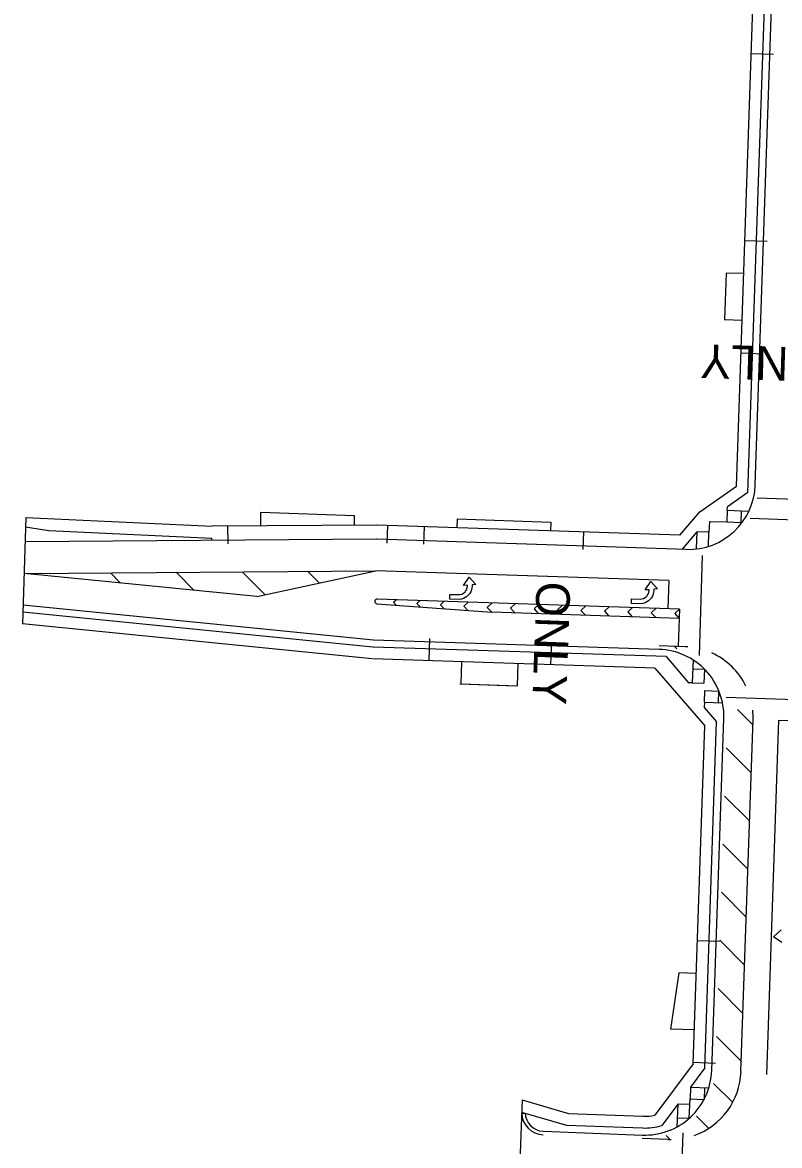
# Model space of a CAD drawing. Extents: x 979036 to 996074, y 1836928 to 1845163.
# Drawn here: x 992166.6 to 992489.6, y 1843156.7 to 1843635.7 of the extents above; entities that cross this region are included whole.
import ezdxf

# ---------------------------------------------------------------- set-up
doc = ezdxf.new("R2010")
doc.units = 0
for name, color, linetype in [('R_Proposed Road', 7, 'Continuous'), ('R_Striping', 7, 'Continuous'), ('STRIPE_White Crosswalk', 7, 'Continuous'), ('STRIPE_White Stopbar', 7, 'Continuous'), ('STRIPE_White Turn Arrow', 7, 'Continuous'), ('STRIPE_White_6in', 7, 'Continuous'), ('STRIPE_White_ONLY', 7, 'Continuous'), ('STRIPE_Yellow Dbl 6in', 7, 'Continuous'), ('STRIPE_Yellow_45_Diag_8in', 7, 'Continuous')]:
    doc.layers.add(name, color=color, linetype=linetype)

msp = doc.modelspace()

# ---------------------------------------------------------------- linework, layer by layer
at = {"layer": 'R_Proposed Road'}
for p, q in [((992471.17, 1843437.97), (992479.58, 1843683.42)), ((992476.08, 1843435.17), (992484.58, 1843683.25)), ((992479.19, 1843438.47), (992487.58, 1843683.15)), ((992477.5, 1843622.5), (992486.99, 1843622.17)), ((992484.25, 1843542.22), (992474.75, 1843542.55)), ((992466.78, 1843528.81), (992466.09, 1843508.82)), ((992474.27, 1843528.56), (992466.78, 1843528.81)), ((992473.59, 1843508.57), (992466.09, 1843508.82)), ((992482.6, 1843494.25), (992473.11, 1843494.58)), ((992455.58, 1843427.05), (992471.17, 1843437.97)), ((992476.08, 1843435.17), (992467.29, 1843429.15)), ((992268.3, 1843420.94), (992268.26, 1843426.82)), ((992268.26, 1843426.82), (992308.27, 1843425.46)), ((992447.07, 1843417.05), (992455.58, 1843427.05)), ((992467.24, 1843427.65), (992467.07, 1843422.65)), ((992467.24, 1843427.65), (992467.29, 1843429.15)), ((992467.24, 1843427.65), (992473.24, 1843427.44)), ((992473.24, 1843427.44), (992473.07, 1843422.45)), ((992473.24, 1843427.44), (992476.5, 1843427.33)), ((992168.12, 1843424.51), (992166.64, 1843379.22)), ((992168.12, 1843424.51), (992247.51, 1843420.8)), ((992308.3, 1843421.23), (992308.27, 1843425.46)), ((992352.07, 1843423.97), (992351.94, 1843420.18)), ((992352.07, 1843423.97), (992392.05, 1843422.64)), ((992392.05, 1843422.64), (992391.92, 1843418.87)), ((992459.61, 1843422.91), (992459.45, 1843418.25)), ((992459.61, 1843422.91), (992467.07, 1843422.65)), ((992467.07, 1843422.65), (992473.07, 1843422.45)), ((992473.07, 1843422.45), (992473.57, 1843422.43)), ((992167.99, 1843420.52), (992177.95, 1843419.05)), ((992177.95, 1843419.05), (992247.41, 1843415.79)), ((992317.81, 1843421.3), (992247.51, 1843420.8)), ((992254.36, 1843413.34), (992254.3, 1843420.84)), ((992447.07, 1843417.05), (992317.96, 1843421.29)), ((992322.3, 1843421.15), (992322.06, 1843413.66)), ((992337.95, 1843420.64), (992337.71, 1843413.14)), ((992405.92, 1843418.41), (992405.67, 1843410.91)), ((992448.21, 1843411.01), (992454.45, 1843418.42)), ((992454.2, 1843411.16), (992454.45, 1843418.42)), ((992459.45, 1843418.25), (992454.45, 1843418.42)), ((992459.24, 1843412.26), (992459.45, 1843418.25)), ((992317.71, 1843415.3), (992167.78, 1843414.22)), ((992247.41, 1843414.79), (992247.41, 1843415.79)), ((992449.77, 1843410.96), (992317.77, 1843415.3)), ((992454.2, 1843411.16), (992454.34, 1843415.16)), ((992316.11, 1843369.33), (992166.8, 1843384.22)), ((992316.31, 1843372.32), (992166.9, 1843387.23)), ((992315.78, 1843364.33), (992166.64, 1843379.22)), ((992441.16, 1843365.22), (992316.26, 1843369.32)), ((992438.22, 1843368.32), (992316.36, 1843372.32)), ((992340.08, 1843363.54), (992340.39, 1843373.03)), ((992392.05, 1843361.83), (992392.36, 1843371.33)), ((992436.43, 1843360.37), (992316.09, 1843364.32)), ((992441.16, 1843365.22), (992450.7, 1843354.12)), ((992353.76, 1843353.58), (992354.07, 1843363.08)), ((992377.75, 1843352.76), (992378.06, 1843362.29)), ((992436.43, 1843360.37), (992457.65, 1843335.68)), ((992452.65, 1843363.84), (992452.33, 1843354.07)), ((992452.53, 1843360.06), (992457.52, 1843359.9)), ((992457.52, 1843359.9), (992457.33, 1843353.9)), ((992353.16, 1843353.6), (992377.14, 1843352.78)), ((992353.76, 1843353.58), (992377.75, 1843352.76)), ((992452.33, 1843354.07), (992450.7, 1843354.12)), ((992452.33, 1843354.07), (992457.33, 1843353.9)), ((992457.53, 1843345.76), (992457.7, 1843350.76)), ((992457.7, 1843350.76), (992463.69, 1843350.55)), ((992463.52, 1843345.55), (992463.69, 1843350.55)), ((992457.53, 1843345.76), (992457.45, 1843343.59)), ((992457.53, 1843345.76), (992465.22, 1843345.5)), ((992457.45, 1843343.59), (992462.72, 1843337.46)), ((992452.71, 1843191.6), (992457.65, 1843335.68)), ((992457.66, 1843189.87), (992462.72, 1843337.46)), ((992460.62, 1843188.73), (992465.77, 1843338.86)), ((992464.01, 1843243.74), (992454.51, 1843244.07)), ((992446.54, 1843230.33), (992443.05, 1843206.44)), ((992454.03, 1843230.07), (992446.54, 1843230.33)), ((992453.21, 1843206.09), (992443.05, 1843206.44)), ((992462.23, 1843191.77), (992452.73, 1843192.1)), ((992452.71, 1843191.6), (992436.39, 1843169.66)), ((992457.64, 1843189.84), (992451.53, 1843181.63)), ((992451.53, 1843181.63), (992451.36, 1843176.63)), ((992451.53, 1843181.63), (992459.39, 1843181.36)), ((992457.52, 1843181.43), (992457.35, 1843176.43)), ((992379.76, 1843176.2), (992377.63, 1843121.23)), ((992379.76, 1843176.2), (992399.55, 1843170.46)), ((992446.27, 1843174.57), (992439.34, 1843165.25)), ((992445.89, 1843164.75), (992446.27, 1843174.57)), ((992446.27, 1843174.57), (992451.27, 1843174.37)), ((992451.04, 1843168.38), (992451.36, 1843176.63)), ((992451.36, 1843176.63), (992457.35, 1843176.43)), ((992379.56, 1843171.05), (992398.74, 1843165.48)), ((992379.56, 1843170.57), (992381.06, 1843170.61)), ((992399.55, 1843170.46), (992431.35, 1843169.23)), ((992446.04, 1843168.57), (992451.04, 1843168.38)), ((992398.74, 1843165.48), (992431.15, 1843164.23)), ((992388.75, 1843162.87), (992431.04, 1843161.23))]:
    msp.add_line(p, q, dxfattribs=at)
for centre, radius, start, end in [((992450.71, 1843439.45), 28.5, 268.1194, 358.0361), ((992437.29, 1843339.83), 28.5, 358.0361, 88.1194), ((992432.14, 1843189.71), 28.5, 267.7861, 358.0361), ((992389.06, 1843170.86), 9.5, 181.7845, 267.7861), ((992389.06, 1843170.86), 8, 181.7845, 267.7861), ((992432.14, 1843189.71), 20.5, 267.7861, 281.9633), ((992432.14, 1843189.71), 25.5, 267.7861, 286.4071)]:
    msp.add_arc(centre, radius, start, end, dxfattribs=at)
at = {"layer": 'R_Striping'}
for p, q in [((992167.34, 1843400.73), (992317.32, 1843401.8)), ((992266.65, 1843390.82), (992167.34, 1843400.73)), ((992266.65, 1843390.82), (992317.32, 1843401.8))]:
    msp.add_line(p, q, dxfattribs=at)
at = {"layer": 'STRIPE_White Crosswalk'}
for p, q in [((992477.09, 1843424.27), (992524.25, 1843422.65)), ((992456.61, 1843408.38), (992455.21, 1843365.68)), ((992466.81, 1843347.94), (992516.55, 1843346.31)), ((992448.3, 1843162.21), (992447.25, 1843135.19))]:
    msp.add_line(p, q, dxfattribs=at)
at = {"layer": 'STRIPE_White Stopbar'}
for p, q in [((992480.01, 1843433.01), (992496.49, 1843432.45)), ((992442.26, 1843397.7), (992441.86, 1843385.71)), ((992446.86, 1843385.54), (992446.34, 1843369.55)), ((992489.26, 1843338.17), (992516.24, 1843337.24))]:
    msp.add_line(p, q, dxfattribs=at)
at = {"layer": 'STRIPE_White Turn Arrow'}
for points in [[(992354.77, 1843395.51), (992357.12, 1843399.18), (992360.08, 1843395.97), (992358.42, 1843395.83), (992358.41, 1843395.16), (992358.37, 1843394.58), (992358.2, 1843393.78), (992357.82, 1843392.85), (992357.4, 1843392.12), (992356.85, 1843391.53), (992356.21, 1843390.84), (992355.52, 1843390.45), (992354.77, 1843390.03), (992353.83, 1843389.77), (992352.84, 1843389.62), (992348.94, 1843389.73), (992348.99, 1843391.73), (992352.58, 1843391.67), (992353.27, 1843391.71), (992354.01, 1843391.92), (992354.79, 1843392.29), (992355.44, 1843392.86), (992355.66, 1843393.16), (992356.04, 1843393.77), (992356.29, 1843394.53), (992356.41, 1843395.26), (992356.43, 1843395.65)], [(992432.25, 1843393.65), (992434.61, 1843397.32), (992437.56, 1843394.11), (992435.9, 1843393.96), (992435.9, 1843393.3), (992435.85, 1843392.72), (992435.68, 1843391.92), (992435.3, 1843390.98), (992434.88, 1843390.25), (992434.33, 1843389.67), (992433.69, 1843388.98), (992433, 1843388.59), (992432.25, 1843388.16), (992431.31, 1843387.9), (992430.33, 1843387.76), (992426.42, 1843387.86), (992426.47, 1843389.87), (992430.06, 1843389.81), (992430.75, 1843389.85), (992431.49, 1843390.06), (992432.27, 1843390.43), (992432.92, 1843391), (992433.14, 1843391.29), (992433.52, 1843391.91), (992433.78, 1843392.67), (992433.9, 1843393.4), (992433.91, 1843393.79)]]:
    msp.add_lwpolyline(points, close=True, dxfattribs=at)
msp.add_lwpolyline([(992490.53, 1843243.38), (992486.91, 1843245.81), (992490.19, 1843248.69)], dxfattribs=at)
at = {"layer": 'STRIPE_White_6in'}
for p, q in [((992446.88, 1843385.54), (992317.93, 1843389.78)), ((992324.91, 1843388.4), (992326.1, 1843389.51)), ((992324.91, 1843388.4), (992326.06, 1843387.17)), ((992334.9, 1843387.87), (992336.29, 1843389.17)), ((992344.89, 1843387.34), (992346.49, 1843388.84)), ((992354.88, 1843386.81), (992356.69, 1843388.51)), ((992364.86, 1843386.24), (992366.93, 1843388.17)), ((992317.82, 1843387.78), (992366.77, 1843384.17)), ((992334.9, 1843387.87), (992336.26, 1843386.42)), ((992344.89, 1843387.34), (992346.45, 1843385.67)), ((992354.88, 1843386.81), (992356.64, 1843384.92)), ((992364.86, 1843386.24), (992366.8, 1843384.17)), ((992446.75, 1843381.55), (992366.77, 1843384.17)), ((992374.86, 1843385.91), (992376.92, 1843387.84)), ((992374.86, 1843385.91), (992376.79, 1843383.84)), ((992384.85, 1843385.58), (992386.92, 1843387.51)), ((992384.85, 1843385.58), (992386.78, 1843383.51)), ((992394.85, 1843385.25), (992396.91, 1843387.18)), ((992394.85, 1843385.25), (992396.78, 1843383.19)), ((992404.84, 1843384.92), (992406.9, 1843386.86)), ((992404.84, 1843384.92), (992406.77, 1843382.86)), ((992414.84, 1843384.59), (992416.9, 1843386.53)), ((992414.84, 1843384.59), (992416.77, 1843382.53)), ((992424.83, 1843384.27), (992426.89, 1843386.2)), ((992424.83, 1843384.27), (992426.76, 1843382.2)), ((992434.82, 1843383.94), (992436.89, 1843385.87)), ((992434.82, 1843383.94), (992436.89, 1843385.87)), ((992434.82, 1843383.94), (992436.76, 1843381.87)), ((992434.82, 1843383.94), (992436.76, 1843381.87)), ((992444.82, 1843383.61), (992446.88, 1843385.54)), ((992444.82, 1843383.61), (992446.75, 1843381.55)), ((992449.26, 1843369.46), (992438.27, 1843369.82)), ((992444.74, 1843369.61), (992445.73, 1843368.62)), ((992471.61, 1843342.74), (992478.18, 1843336.17)), ((992473.11, 1843188.26), (992478.26, 1843338.45)), ((992466.84, 1843326.3), (992477.48, 1843315.66)), ((992466.14, 1843305.79), (992476.78, 1843295.15)), ((992465.43, 1843285.28), (992476.07, 1843274.64)), ((992464.73, 1843264.77), (992475.37, 1843254.13)), ((992464.03, 1843244.26), (992474.67, 1843233.62)), ((992463.32, 1843223.75), (992473.96, 1843213.11)), ((992462.62, 1843203.24), (992473.26, 1843192.6)), ((992461.43, 1843183.22), (992469.56, 1843175.09)), ((992454.13, 1843169.3), (992459.37, 1843164.06)), ((992441.97, 1843159.31), (992430.98, 1843159.73)), ((992441.13, 1843161.09), (992442.93, 1843159.29))]:
    msp.add_line(p, q, dxfattribs=at)
for centre, radius, start, end in [((992317.9, 1843388.78), 1, 88.1194, 265.7831), ((992448.28, 1843339.47), 30, 86.0169, 88.1194), ((992448.28, 1843339.47), 30, 26.0953, 65.6481), ((992448.28, 1843339.47), 30, 358.0361, 5.6659), ((992443.13, 1843189.29), 30, 289.5759, 358.0361), ((992443.13, 1843189.29), 30, 267.7861, 270.2732)]:
    msp.add_arc(centre, radius, start, end, dxfattribs=at)
at = {"layer": 'STRIPE_Yellow Dbl 6in'}
for p, q in [((992167.34, 1843400.73), (992317.32, 1843401.8)), ((992266.65, 1843390.82), (992167.34, 1843400.73)), ((992266.65, 1843390.82), (992317.32, 1843401.8)), ((992442.26, 1843397.7), (992317.32, 1843401.8)), ((992484.08, 1843187.02), (992489.26, 1843338.17))]:
    msp.add_line(p, q, dxfattribs=at)
at = {"layer": 'STRIPE_Yellow_45_Diag_8in'}
for p, q in [((992208.49, 1843396.62), (992204.12, 1843400.99)), ((992239.91, 1843393.48), (992232.2, 1843401.19)), ((992270.11, 1843391.57), (992260.28, 1843401.39)), ((992293.36, 1843396.61), (992288.37, 1843401.6)), ((992316.6, 1843401.65), (992316.45, 1843401.8))]:
    msp.add_line(p, q, dxfattribs=at)

# ---------------------------------------------------------------- texts
at = {"layer": 'STRIPE_White_ONLY'}
for rotation, p in [(178.1709, (992508.54, 1843496.78)), (267.9663, (992385.96, 1843397.41))]:
    msp.add_text('ONLY', height=14.4, rotation=rotation, dxfattribs=at).set_placement(p)

doc.saveas('drawing.dxf')
